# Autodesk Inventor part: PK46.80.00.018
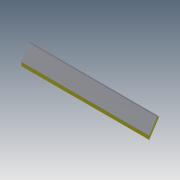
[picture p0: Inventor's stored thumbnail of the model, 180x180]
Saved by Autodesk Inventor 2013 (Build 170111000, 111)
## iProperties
Shininess: 64.0
Length Units: 11269
Angle Units: 11279
Time Units: 11290
Mass Units: 11283
Length Display Precision: 3
Angle Display Precision: 2
Compacted: True
Part Number: PK46.80.00.018
Document SubType Name: Modeling
Created: 2005-01
Material: Steel, Mild
Designer: SAlex
Manufacturer: Standard
Standards Organization: Custom
Density: 7.86 g/cm^3
Density: 0.0
Volumn: 0.0
Area: 0.0
PropertySet Name: Model Information
Control State: 0
Master: False
Checked Out: False
Checked Out Date: 2008-10-15
Last Check In Date: 2008-10-15
Author: SAlex
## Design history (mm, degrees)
sketch "Sketch1"
  geometry: L1 (0, 0)-(677, 0); L2 (677, 0)-(752, -125); L3 (752, -125)-(75, -125); L4 (75, -125)-(0, 0)
  constraints: 8 end point, 2 parallel, 1 horizontal, 1 other
  dimensions: "d0" = 677 distance of L1.start L1.end; "d1" = 125 distance between parallel lines of L3 L1; "d2" = 75 horizontal distance of L3.end L1.start
extrude "Extrusion1" new body sketch "Sketch1" distance "d3" = 19; taper "d4" = 0 deg
chamfer "Chamfer1" distance "d5" = 10; stored, may be unused: angle "d6" = 60 deg, second distance "d7" = 10
body "Solid1"
